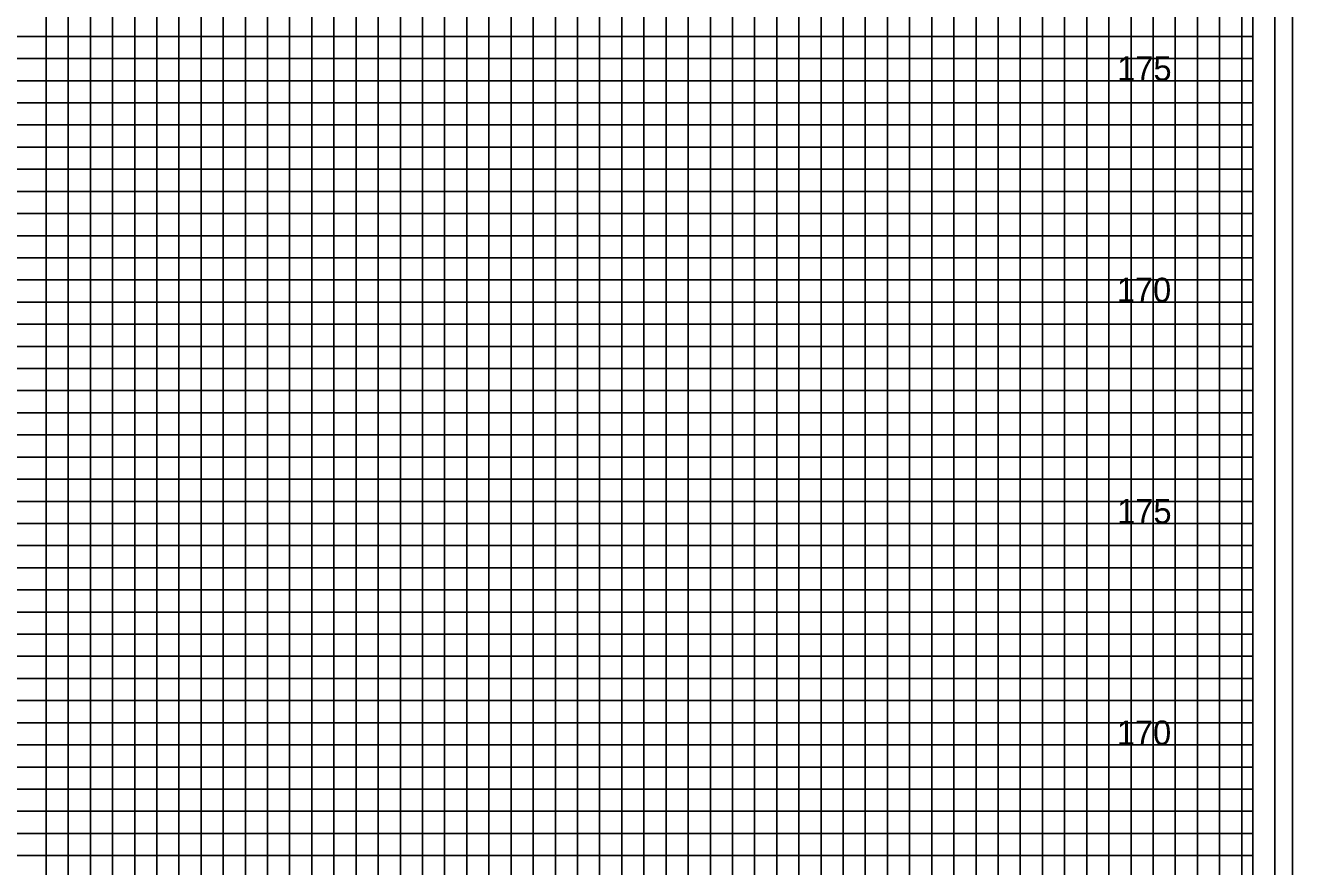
# Model space of a CAD drawing. Extents: x -4 to 103, y -2 to 209.
# Drawn here: x 74.78 to 103.4, y 173.9 to 192.9 of the extents above; entities that cross this region are included whole.
import ezdxf

# ---------------------------------------------------------------- set-up
doc = ezdxf.new("R2010")
doc.units = 0
for name, color, linetype in [('Prop XS Elevation Labels', 7, 'Continuous'), ('Sheet Cross Section CELL', 7, 'Continuous'), ('Sheet Cross Section Grid Major CELL', 7, 'Continuous'), ('Sheet Cross Section Grid Middle CELL', 7, 'Continuous'), ('Sheet DOT Grid CELL', 7, 'Continuous'), ('Sheet Plot Border Inside CELL', 7, 'Continuous'), ('Sheet Plot Border Outside CELL', 7, 'Continuous')]:
    doc.layers.add(name, color=color, linetype=linetype)

msp = doc.modelspace()

# ---------------------------------------------------------------- linework, layer by layer
at = {"layer": 'Sheet Cross Section CELL'}
msp.add_lwpolyline([(102.5, 206.65), (0, 206.65), (0, 141.65), (102.5, 141.65)], close=True, dxfattribs=at)
at = {"layer": 'Sheet Cross Section Grid Major CELL'}
for points in [[(91.25, 141.65), (91.25, 205.075), (93.75, 205.075), (93.75, 141.65)], [(96.25, 141.65), (96.25, 205.075), (98.75, 205.075), (98.75, 141.65)], [(101.25, 141.65), (101.25, 205.075)], [(76.25, 141.65), (76.25, 203.65), (78.75, 203.65), (78.75, 141.65)], [(81.25, 141.65), (81.25, 203.65), (83.75, 203.65), (83.75, 141.65)], [(86.25, 141.65), (86.25, 203.65), (88.75, 203.65), (88.75, 141.65)], [(0, 189.15), (102.5, 189.15), (102.5, 191.65), (0, 191.65)], [(0, 184.15), (102.5, 184.15), (102.5, 186.65), (0, 186.65)], [(0, 179.15), (102.5, 179.15), (102.5, 181.65), (0, 181.65)], [(0, 174.15), (102.5, 174.15), (102.5, 176.65), (0, 176.65)]]:
    msp.add_lwpolyline(points, dxfattribs=at)
at = {"layer": 'Sheet Cross Section Grid Middle CELL'}
for points in [[(90.25, 141.65), (90.25, 205.075), (90.75, 205.075), (90.75, 141.65)], [(91.75, 141.65), (91.75, 205.075), (92.25, 205.075), (92.25, 141.65)], [(92.75, 141.65), (92.75, 205.075), (93.25, 205.075), (93.25, 141.65)], [(94.25, 141.65), (94.25, 205.075), (94.75, 205.075), (94.75, 141.65)], [(95.25, 141.65), (95.25, 205.075), (95.75, 205.075), (95.75, 141.65)], [(96.75, 141.65), (96.75, 205.075), (97.25, 205.075), (97.25, 141.65)], [(97.75, 141.65), (97.75, 205.075), (98.25, 205.075), (98.25, 141.65)], [(99.25, 141.65), (99.25, 205.075), (99.75, 205.075), (99.75, 141.65)], [(100.25, 141.65), (100.25, 205.075)], [(100.25, 205.075), (100.75, 205.075), (100.75, 141.65), (101.75, 141.65), (101.75, 205.075), (102.25, 205.075), (102.25, 141.65)], [(75.25, 141.65), (75.25, 203.65), (75.75, 203.65), (75.75, 141.65)], [(76.75, 141.65), (76.75, 203.65), (77.25, 203.65), (77.25, 141.65)], [(77.75, 141.65), (77.75, 203.65), (78.25, 203.65), (78.25, 141.65)], [(79.25, 141.65), (79.25, 203.65), (79.75, 203.65), (79.75, 141.65)], [(80.25, 141.65), (80.25, 203.65), (80.75, 203.65), (80.75, 141.65)], [(81.75, 141.65), (81.75, 203.65), (82.25, 203.65), (82.25, 141.65)], [(82.75, 141.65), (82.75, 203.65), (83.25, 203.65), (83.25, 141.65)], [(84.25, 141.65), (84.25, 203.65), (84.75, 203.65), (84.75, 141.65)], [(85.25, 141.65), (85.25, 203.65), (85.75, 203.65), (85.75, 141.65)], [(86.75, 141.65), (86.75, 203.65), (87.25, 203.65), (87.25, 141.65)], [(87.75, 141.65), (87.75, 203.65), (88.25, 203.65), (88.25, 141.65)], [(89.25, 141.65), (89.25, 203.65), (89.75, 203.65), (89.75, 141.65)], [(0, 192.15), (102.5, 192.15), (102.5, 192.65), (0, 192.65)], [(0, 190.65), (102.5, 190.65), (102.5, 191.15), (0, 191.15)], [(0, 189.65), (102.5, 189.65), (102.5, 190.15), (0, 190.15)], [(0, 188.15), (102.5, 188.15), (102.5, 188.65), (0, 188.65)], [(0, 187.15), (102.5, 187.15), (102.5, 187.65), (0, 187.65)], [(0, 185.65), (102.5, 185.65), (102.5, 186.15), (0, 186.15)], [(0, 184.65), (102.5, 184.65), (102.5, 185.15), (0, 185.15)], [(0, 183.15), (102.5, 183.15), (102.5, 183.65), (0, 183.65)], [(0, 182.15), (102.5, 182.15), (102.5, 182.65), (0, 182.65)], [(0, 180.65), (102.5, 180.65), (102.5, 181.15), (0, 181.15)], [(0, 179.65), (102.5, 179.65), (102.5, 180.15), (0, 180.15)], [(0, 178.15), (102.5, 178.15), (102.5, 178.65), (0, 178.65)], [(0, 177.15), (102.5, 177.15), (102.5, 177.65), (0, 177.65)], [(0, 175.65), (102.5, 175.65), (102.5, 176.15), (0, 176.15)], [(0, 174.65), (102.5, 174.65), (102.5, 175.15), (0, 175.15)]]:
    msp.add_lwpolyline(points, dxfattribs=at)
at = {"layer": 'Sheet DOT Grid CELL'}
for p, q in [((91.25, 141.65), (91.25, 205.075)), ((93.75, 141.65), (93.75, 205.075)), ((96.25, 141.65), (96.25, 205.075)), ((98.75, 141.65), (98.75, 205.075)), ((101.25, 141.65), (101.25, 205.075)), ((76.25, 141.65), (76.25, 203.65)), ((78.75, 141.65), (78.75, 203.65)), ((81.25, 141.65), (81.25, 203.65)), ((83.75, 141.65), (83.75, 203.65)), ((86.25, 141.65), (86.25, 203.65)), ((88.75, 141.65), (88.75, 203.65)), ((0, 191.65), (102.5, 191.65)), ((0, 189.15), (102.5, 189.15)), ((0, 186.65), (102.5, 186.65)), ((0, 184.15), (102.5, 184.15)), ((0, 181.65), (102.5, 181.65)), ((0, 179.15), (102.5, 179.15)), ((0, 176.65), (102.5, 176.65)), ((0, 174.15), (102.5, 174.15))]:
    msp.add_line(p, q, dxfattribs=at)
at = {"layer": 'Sheet Plot Border Inside CELL'}
msp.add_lwpolyline([(103, 207.65), (-2.8, 207.65), (-2.8, 140.65), (103, 140.65)], close=True, dxfattribs=at)
at = {"layer": 'Sheet Plot Border Outside CELL'}
msp.add_lwpolyline([(103.4, 209.05), (-3.5, 209.05), (-3.5, 139.225), (103.4, 139.225)], close=True, dxfattribs=at)

# ---------------------------------------------------------------- texts
at = {"layer": 'Prop XS Elevation Labels'}
for s, p in [('175', (99.43825, 191.65)), ('170', (99.42958, 186.65)), ('175', (99.43825, 181.65)), ('170', (99.42958, 176.65))]:
    msp.add_text(s, height=0.55, dxfattribs=at).set_placement(p)

doc.saveas('drawing.dxf')
